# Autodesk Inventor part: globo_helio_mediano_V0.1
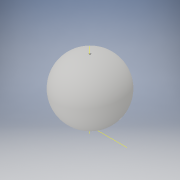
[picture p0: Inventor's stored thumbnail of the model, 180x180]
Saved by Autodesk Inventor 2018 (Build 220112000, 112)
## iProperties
Created: 2018-09
Part Number: globo_helio_mediano_V0.1
Material: Generic
Document SubType Name: Modeling
Designer: Gordillo
Density: 1 g/cm^3
Appearance: Default
Author: Gordillo
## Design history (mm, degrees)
sketch "Sketch2"
  geometry: L1 (0, -800)-(0, 4800) reference; L2 (-392, 0)-(2352, 0) reference; L3 (50, 0)-(50, 180); L4 (0, 4000)-(50, 4000); A1 r 1910 centre (50, 2090) between (50, 180) and (50, 4000); 1 further point
  constraints: 4 end point, 2 point on circle, 2 point on line, 1 centre point, 1 horizontal, 1 line through centre, 1 vertical
  dimensions: "d0" = 180 distance of L3.start L3.end; "d1" = 50 distance between parallel lines of L1 L3; "d2" = 4000 distance of point (0, 0) L4.start; "d3" = 50 distance of L4.start L4.end
revolve "Revolution1" sketch "Sketch2" stored, may be unused: angle "d4" = 90 deg
body "Solid1"
